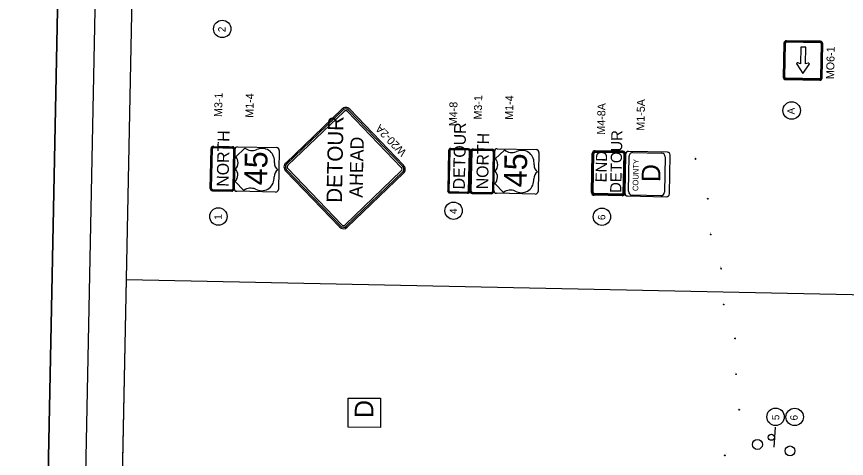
# Model space of a CAD drawing. Extents: x 327762 to 372792, y 127949 to 259367.
# Drawn here: x 344443 to 358431, y 195702 to 203152 of the extents above; entities that cross this region are included whole.
import ezdxf

# ---------------------------------------------------------------- set-up
doc = ezdxf.new("R2010")
doc.units = 0
for name, color, linetype in [('CA-TEXT', 7, 'Continuous'), ('CE-TOPO-CONC-SLAB', 7, 'Continuous'), ('E_SOIL_BORE1 [KAPUR_CADDS_LEVELS]', 7, 'Continuous'), ('E_SOIL_BORE2 [KAPUR_CADDS_LEVELS]', 7, 'Continuous'), ('P_MARK', 7, 'Continuous'), ('P_MISC_NoPlot', 7, 'Continuous'), ('P_RDWY_Text', 7, 'Continuous'), ('P_SGN_Cell', 7, 'Continuous'), ('PLT_Sheet_Border', 7, 'Continuous'), ('PLT_Sheet_Info', 7, 'Continuous'), ('SIGNS-POLES', 7, 'Continuous')]:
    doc.layers.add(name, color=color, linetype=linetype)

msp = doc.modelspace()

# ---------------------------------------------------------------- linework, layer by layer
at = {"layer": 'CA-TEXT'}
msp.add_line((350299, 196481), (350299, 196481), dxfattribs=at)
msp.add_lwpolyline([(350578, 196224), (350031, 196226), (350033, 196717), (350580, 196715)], close=True, dxfattribs=at)
for centre in [(347909, 202944), (357509, 201568), (347845, 199781), (351809, 199878), (354310, 199777), (357237, 196403), (357559, 196401)]:
    msp.add_circle(centre, 147, dxfattribs=at)
at = {"layer": 'CE-TOPO-CONC-SLAB'}
for centre in [(356932, 195937), (357481, 195828)]:
    msp.add_circle(centre, 83.7, dxfattribs=at)
at = {"layer": 'P_MARK'}
for p, q in [((355883, 200752), (355893, 200752)), ((355888, 200757), (355888, 200747)), ((356091, 200081), (356101, 200081)), ((356096, 200086), (356096, 200076)), ((356144, 199481), (356144, 199471)), ((356139, 199476), (356149, 199476)), ((356314, 198901), (356324, 198901)), ((356319, 198906), (356319, 198896)), ((356359, 198295), (356369, 198295)), ((356364, 198300), (356364, 198290)), ((356549, 197724), (356559, 197724)), ((356554, 197729), (356554, 197719)), ((356567, 197121), (356577, 197121)), ((356572, 197126), (356572, 197116)), ((356618, 196522), (356628, 196522)), ((356623, 196527), (356623, 196517)), ((356377, 195752), (356387, 195752)), ((356382, 195757), (356382, 195747))]:
    msp.add_line(p, q, dxfattribs=at)
for centre in [(355888, 200752), (356096, 200081), (356144, 199476), (356319, 198901), (356364, 198295), (356554, 197724), (356572, 197121), (356623, 196522), (356382, 195752)]:
    msp.add_circle(centre, 5, dxfattribs=at)
for centre, radius, start, end in [((355888, 200752), 4.5, 89.9869, 179.9869), ((355888, 200752), 4, 89.9869, 179.9869), ((355888, 200752), 3.5, 89.9869, 179.9869), ((355888, 200752), 3, 89.9869, 179.9869), ((355888, 200752), 2.5, 89.9869, 179.9869), ((355888, 200752), 2, 89.9869, 179.9869), ((355888, 200752), 1.5, 89.9869, 179.9869), ((355888, 200752), 1, 89.9869, 179.9869), ((355888, 200752), 0.5, 89.9869, 179.9869), ((355888, 200752), 4.5, 269.9869, 359.9869), ((355888, 200752), 4, 269.9869, 359.9869), ((355888, 200752), 3.5, 269.9869, 359.9869), ((355888, 200752), 3, 269.9869, 359.9869), ((355888, 200752), 2.5, 269.9869, 359.9869), ((355888, 200752), 2, 269.9869, 359.9869), ((355888, 200752), 1.5, 269.9869, 359.9869), ((355888, 200752), 1, 269.9869, 359.9869), ((355888, 200752), 0.5, 269.9869, 359.9869), ((356096, 200081), 4.5, 89.9869, 179.9869), ((356096, 200081), 4, 89.9869, 179.9869), ((356096, 200081), 3.5, 89.9869, 179.9869), ((356096, 200081), 3, 89.9869, 179.9869), ((356096, 200081), 2.5, 89.9869, 179.9869), ((356096, 200081), 2, 89.9869, 179.9869), ((356096, 200081), 1.5, 89.9869, 179.9869), ((356096, 200081), 1, 89.9869, 179.9869), ((356096, 200081), 0.5, 89.9869, 179.9869), ((356096, 200081), 4.5, 269.9869, 359.9869), ((356096, 200081), 4, 269.9869, 359.9869), ((356096, 200081), 3.5, 269.9869, 359.9869), ((356096, 200081), 3, 269.9869, 359.9869), ((356096, 200081), 2.5, 269.9869, 359.9869), ((356096, 200081), 2, 269.9869, 359.9869), ((356096, 200081), 1.5, 269.9869, 359.9869), ((356096, 200081), 1, 269.9869, 359.9869), ((356096, 200081), 0.5, 269.9869, 359.9869), ((356144, 199476), 4.5, 89.9869, 179.9869), ((356144, 199476), 4, 89.9869, 179.9869), ((356144, 199476), 3.5, 89.9869, 179.9869), ((356144, 199476), 3, 89.9869, 179.9869), ((356144, 199476), 2.5, 89.9869, 179.9869), ((356144, 199476), 2, 89.9869, 179.9869), ((356144, 199476), 1.5, 89.9869, 179.9869), ((356144, 199476), 1, 89.9869, 179.9869), ((356144, 199476), 0.5, 89.9869, 179.9869), ((356144, 199476), 4.5, 269.9869, 359.9869), ((356144, 199476), 4, 269.9869, 359.9869), ((356144, 199476), 3.5, 269.9869, 359.9869), ((356144, 199476), 3, 269.9869, 359.9869), ((356144, 199476), 2.5, 269.9869, 359.9869), ((356144, 199476), 2, 269.9869, 359.9869), ((356144, 199476), 1.5, 269.9869, 359.9869), ((356144, 199476), 1, 269.9869, 359.9869), ((356144, 199476), 0.5, 269.9869, 359.9869), ((356319, 198901), 4.5, 89.9869, 179.9869), ((356319, 198901), 4, 89.9869, 179.9869), ((356319, 198901), 3.5, 89.9869, 179.9869), ((356319, 198901), 3, 89.9869, 179.9869), ((356319, 198901), 2.5, 89.9869, 179.9869), ((356319, 198901), 2, 89.9869, 179.9869), ((356319, 198901), 1.5, 89.9869, 179.9869), ((356319, 198901), 1, 89.9869, 179.9869), ((356319, 198901), 0.5, 89.9869, 179.9869), ((356319, 198901), 4.5, 269.9869, 359.9869), ((356319, 198901), 4, 269.9869, 359.9869), ((356319, 198901), 3.5, 269.9869, 359.9869), ((356319, 198901), 3, 269.9869, 359.9869), ((356319, 198901), 2.5, 269.9869, 359.9869), ((356319, 198901), 2, 269.9869, 359.9869), ((356319, 198901), 1.5, 269.9869, 359.9869), ((356319, 198901), 1, 269.9869, 359.9869), ((356319, 198901), 0.5, 269.9869, 359.9869), ((356364, 198295), 4.5, 89.9869, 179.9869), ((356364, 198295), 4, 89.9869, 179.9869), ((356364, 198295), 3.5, 89.9869, 179.9869), ((356364, 198295), 3, 89.9869, 179.9869), ((356364, 198295), 2.5, 89.9869, 179.9869), ((356364, 198295), 2, 89.9869, 179.9869), ((356364, 198295), 1.5, 89.9869, 179.9869), ((356364, 198295), 1, 89.9869, 179.9869), ((356364, 198295), 0.5, 89.9869, 179.9869), ((356364, 198295), 4.5, 269.9869, 359.9869), ((356364, 198295), 4, 269.9869, 359.9869), ((356364, 198295), 3.5, 269.9869, 359.9869), ((356364, 198295), 3, 269.9869, 359.9869), ((356364, 198295), 2.5, 269.9869, 359.9869), ((356364, 198295), 2, 269.9869, 359.9869), ((356364, 198295), 1.5, 269.9869, 359.9869), ((356364, 198295), 1, 269.9869, 359.9869), ((356364, 198295), 0.5, 269.9869, 359.9869), ((356554, 197724), 4.5, 89.9869, 179.9869), ((356554, 197724), 4, 89.9869, 179.9869), ((356554, 197724), 3.5, 89.9869, 179.9869), ((356554, 197724), 3, 89.9869, 179.9869), ((356554, 197724), 2.5, 89.9869, 179.9869), ((356554, 197724), 2, 89.9869, 179.9869), ((356554, 197724), 1.5, 89.9869, 179.9869), ((356554, 197724), 1, 89.9869, 179.9869), ((356554, 197724), 0.5, 89.9869, 179.9869), ((356554, 197724), 4.5, 269.9869, 359.9869), ((356554, 197724), 4, 269.9869, 359.9869), ((356554, 197724), 3.5, 269.9869, 359.9869), ((356554, 197724), 3, 269.9869, 359.9869), ((356554, 197724), 2.5, 269.9869, 359.9869), ((356554, 197724), 2, 269.9869, 359.9869), ((356554, 197724), 1.5, 269.9869, 359.9869), ((356554, 197724), 1, 269.9869, 359.9869), ((356554, 197724), 0.5, 269.9869, 359.9869), ((356572, 197121), 4.5, 89.9869, 179.9869), ((356572, 197121), 4, 89.9869, 179.9869), ((356572, 197121), 3.5, 89.9869, 179.9869), ((356572, 197121), 3, 89.9869, 179.9869), ((356572, 197121), 2.5, 89.9869, 179.9869), ((356572, 197121), 2, 89.9869, 179.9869), ((356572, 197121), 1.5, 89.9869, 179.9869), ((356572, 197121), 1, 89.9869, 179.9869), ((356572, 197121), 4.5, 269.9869, 359.9869), ((356572, 197121), 4, 269.9869, 359.9869), ((356572, 197121), 3.5, 269.9869, 359.9869), ((356572, 197121), 3, 269.9869, 359.9869), ((356572, 197121), 2.5, 269.9869, 359.9869), ((356572, 197121), 2, 269.9869, 359.9869), ((356572, 197121), 1.5, 269.9869, 359.9869), ((356572, 197121), 1, 269.9869, 359.9869), ((356572, 197121), 0.5, 269.9869, 359.9869), ((356572, 197121), 0.5, 89.9869, 179.9869), ((356623, 196522), 4.5, 89.9869, 179.9869), ((356623, 196522), 4, 89.9869, 179.9869), ((356623, 196522), 3.5, 89.9869, 179.9869), ((356623, 196522), 3, 89.9869, 179.9869), ((356623, 196522), 2.5, 89.9869, 179.9869), ((356623, 196522), 2, 89.9869, 179.9869), ((356623, 196522), 1.5, 89.9869, 179.9869), ((356623, 196522), 1, 89.9869, 179.9869), ((356623, 196522), 0.5, 89.9869, 179.9869), ((356623, 196522), 4.5, 269.9869, 359.9869), ((356623, 196522), 4, 269.9869, 359.9869), ((356623, 196522), 3.5, 269.9869, 359.9869), ((356623, 196522), 3, 269.9869, 359.9869), ((356623, 196522), 2.5, 269.9869, 359.9869), ((356623, 196522), 2, 269.9869, 359.9869), ((356623, 196522), 1.5, 269.9869, 359.9869), ((356623, 196522), 1, 269.9869, 359.9869), ((356623, 196522), 0.5, 269.9869, 359.9869), ((356382, 195752), 4.5, 89.9869, 179.9869), ((356382, 195752), 4, 89.9869, 179.9869), ((356382, 195752), 3.5, 89.9869, 179.9869), ((356382, 195752), 3, 89.9869, 179.9869), ((356382, 195752), 2.5, 89.9869, 179.9869), ((356382, 195752), 2, 89.9869, 179.9869), ((356382, 195752), 1.5, 89.9869, 179.9869), ((356382, 195752), 1, 89.9869, 179.9869), ((356382, 195752), 0.5, 89.9869, 179.9869), ((356382, 195752), 4.5, 269.9869, 359.9869), ((356382, 195752), 4, 269.9869, 359.9869), ((356382, 195752), 3.5, 269.9869, 359.9869), ((356382, 195752), 3, 269.9869, 359.9869), ((356382, 195752), 2.5, 269.9869, 359.9869), ((356382, 195752), 2, 269.9869, 359.9869), ((356382, 195752), 1.5, 269.9869, 359.9869), ((356382, 195752), 1, 269.9869, 359.9869), ((356382, 195752), 0.5, 269.9869, 359.9869)]:
    msp.add_arc(centre, radius, start, end, dxfattribs=at)
at = {"layer": 'P_MISC_NoPlot'}
msp.add_lwpolyline([(345724, 170440), (346294, 198721), (365051, 198328), (365036, 197298), (370642, 197202), (370093, 169949)], close=True, dxfattribs=at)
at = {"layer": 'P_RDWY_Text'}
msp.add_lwpolyline([(344443, 168885), (345298, 211374), (372792, 210820), (371936, 168331)], close=True, dxfattribs=at)
at = {"layer": 'P_SGN_Cell'}
for p, q in [((357378, 202706), (357366, 202132)), ((357377, 202132), (357389, 202706)), ((357391, 202132), (357403, 202706)), ((357993, 202710), (357419, 202722)), ((357994, 202735), (357420, 202746)), ((357994, 202724), (357420, 202735)), ((357664, 202637), (357658, 202357)), ((357746, 202636), (357664, 202637)), ((357740, 202356), (357746, 202636)), ((357998, 202119), (358010, 202693)), ((358012, 202119), (358023, 202693)), ((358023, 202119), (358034, 202693)), ((357593, 202348), (357696, 202191)), ((357658, 202357), (357611, 202373)), ((357696, 202191), (357805, 202344)), ((357788, 202369), (357740, 202356)), ((357981, 202103), (357407, 202115)), ((357981, 202090), (357407, 202101)), ((357407, 202090), (357981, 202079)), ((347708, 200252), (347721, 200928)), ((347717, 200252), (347731, 200927)), ((347730, 200252), (347743, 200927)), ((347759, 200955), (348084, 200948)), ((347759, 200942), (348084, 200936)), ((347760, 200964), (348084, 200958)), ((348099, 200920), (348086, 200245)), ((348112, 200920), (348098, 200245)), ((348121, 200919), (348108, 200245)), ((348108, 200254), (348121, 200910)), ((348288, 200936), (348136, 200790)), ((348169, 200956), (348825, 200943)), ((348871, 200895), (348864, 200567)), ((348871, 200895), (348871, 200895)), ((352085, 200209), (352098, 200884)), ((352094, 200209), (352107, 200884)), ((352106, 200209), (352120, 200884)), ((352136, 200921), (352461, 200915)), ((352136, 200912), (352461, 200905)), ((352136, 200899), (352461, 200893)), ((352476, 200877), (352463, 200202)), ((352489, 200876), (352475, 200202)), ((352498, 200876), (352484, 200201)), ((352485, 200220), (352498, 200877)), ((352665, 200902), (352513, 200756)), ((352546, 200922), (353202, 200909)), ((354664, 200880), (354196, 200889)), ((354664, 200868), (354196, 200878)), ((355414, 200865), (354758, 200878)), ((353248, 200861), (353241, 200533)), ((353248, 200861), (353248, 200861)), ((354135, 200187), (354148, 200843)), ((354147, 200187), (354160, 200843)), ((354162, 200187), (354175, 200843)), ((354664, 200852), (354195, 200862)), ((354670, 200176), (354683, 200833)), ((354685, 200176), (354699, 200832)), ((354697, 200176), (354710, 200832)), ((354710, 200832), (354697, 200176)), ((354756, 200206), (354768, 200800)), ((354832, 200861), (355316, 200851)), ((355378, 200787), (355366, 200194)), ((355447, 200161), (355460, 200817)), ((348789, 200688), (348790, 200717)), ((353166, 200654), (353167, 200684)), ((348864, 200567), (348858, 200239)), ((353241, 200533), (353235, 200205)), ((348128, 200373), (348273, 200222)), ((348784, 200420), (348784, 200449)), ((352505, 200340), (352650, 200188)), ((353161, 200386), (353161, 200416)), ((347744, 200214), (348069, 200208)), ((347745, 200236), (348070, 200230)), ((347745, 200224), (348070, 200217)), ((348810, 200193), (348154, 200206)), ((352121, 200181), (352446, 200174)), ((352122, 200193), (352447, 200187)), ((352121, 200171), (352446, 200165)), ((353187, 200159), (352531, 200173)), ((354650, 200157), (354181, 200167)), ((354650, 200142), (354181, 200151)), ((354649, 200130), (354181, 200139)), ((354743, 200128), (355399, 200115)), ((355302, 200132), (354818, 200142)), ((355302, 200132), (355302, 200132))]:
    msp.add_line(p, q, dxfattribs=at)
for points in [[(349925, 201592), (348979, 200683)], [(349942, 201575), (348995, 200666)], [(350966, 200644), (350058, 201590)], [(349963, 201554), (349016, 200645)], [(350928, 200607), (350019, 201553)], [(350949, 200628), (350040, 201574)], [(351723, 200892), (351710, 200217)], [(351733, 200891), (351719, 200217)], [(351745, 200891), (351731, 200216)], [(352061, 200922), (351761, 200928)], [(352061, 200913), (351761, 200919)], [(352061, 200900), (351761, 200907)], [(352063, 200210), (352076, 200885)], [(352075, 200209), (352089, 200884)], [(352085, 200209), (352098, 200884)], [(348976, 200551), (349885, 199604)], [(348993, 200567), (349903, 199621)], [(349015, 200588), (349924, 199641)], [(349981, 199640), (350927, 200549)], [(350001, 199619), (350948, 200528)], [(350018, 199602), (350964, 200511)], [(351746, 200179), (352046, 200173)], [(351747, 200200), (352047, 200194)], [(351747, 200188), (352046, 200182)]]:
    msp.add_lwpolyline(points, dxfattribs=at)
for centre, radius, start, end in [((357419, 202705), 41, 88.8462, 178.8462), ((357419, 202705), 30.1, 88.8462, 178.8462), ((357419, 202705), 16.4, 88.8462, 178.8462), ((357993, 202694), 16.4, 358.8462, 88.8462), ((357993, 202694), 41, 358.8462, 88.8462), ((357993, 202694), 30.1, 358.8462, 88.8462), ((357606, 202357), 16.4, 72.0436, 213.3759), ((357792, 202353), 16.4, 324.3166, 105.6488), ((357408, 202131), 41, 178.8462, 268.8462), ((357408, 202131), 30.1, 178.8462, 268.8462), ((357408, 202131), 41, 239.4497, 268.8462), ((357408, 202131), 16.4, 178.8462, 268.8462), ((357982, 202120), 30.1, 268.8462, 358.8462), ((357982, 202120), 41, 268.8462, 358.8462), ((357982, 202120), 16.4, 268.8462, 358.8462), ((349990, 201525), 93.7, 43.8468, 133.8468), ((349990, 201525), 69.9, 43.8468, 133.8468), ((349990, 201525), 40.2, 43.8468, 133.8468), ((347759, 200927), 37.5, 88.8462, 178.8462), ((347759, 200927), 28.1, 88.8462, 178.8462), ((347759, 200927), 15.6, 88.8462, 178.8462), ((348084, 200920), 37.5, 358.8462, 88.8462), ((348084, 200920), 28.1, 358.8462, 88.8462), ((348084, 200920), 15.6, 358.8462, 88.8462), ((348168, 200909), 46.9, 88.8462, 178.8462), ((348413, 201102), 208, 233.1143, 291.9873), ((348581, 200721), 208, 358.8462, 115.6928), ((348824, 200896), 46.9, 358.8462, 88.8462), ((351761, 200891), 37.5, 88.8468, 178.8468), ((351761, 200891), 28.1, 88.8468, 178.8468), ((351761, 200891), 15.6, 88.8468, 178.8468), ((352061, 200885), 37.5, 358.8468, 88.8468), ((352061, 200885), 28.1, 358.8468, 88.8468), ((352061, 200885), 15.6, 358.8468, 88.8468), ((352136, 200884), 37.5, 88.8462, 178.8462), ((352136, 200884), 28.1, 88.8462, 178.8462), ((352136, 200884), 15.6, 88.8462, 178.8462), ((352461, 200877), 37.5, 358.8462, 88.8462), ((352461, 200877), 28.1, 358.8462, 88.8462), ((352461, 200877), 15.6, 358.8462, 88.8462), ((352545, 200876), 46.9, 88.8462, 178.8462), ((352790, 201069), 208, 233.1143, 291.9873), ((352958, 200688), 208, 358.8462, 115.6928), ((353201, 200862), 46.9, 358.8462, 88.8462), ((354195, 200842), 46.9, 88.8468, 178.8468), ((354195, 200842), 35.2, 88.8468, 178.8468), ((354664, 200833), 46.9, 358.8468, 88.8468), ((354757, 200831), 46.9, 88.8462, 178.8462), ((348028, 200688), 149, 314.4191, 43.2734), ((352405, 200654), 149, 314.4191, 43.2734), ((354195, 200842), 19.5, 88.8468, 178.8468), ((354664, 200833), 35.2, 358.8468, 88.8468), ((354664, 200833), 19.5, 358.8468, 88.8468), ((354831, 200798), 62.5, 88.8462, 178.8462), ((355315, 200789), 62.5, 358.8462, 88.8462), ((355413, 200818), 46.9, 358.8462, 88.8462), ((348940, 200685), 151, 179.1885, 231.634), ((349044, 200616), 93.7, 133.8449, 223.8468), ((349044, 200616), 69.9, 133.8449, 223.8468), ((349044, 200616), 40.2, 133.8449, 223.8468), ((350900, 200578), 40.2, 313.854, 44.4977), ((350900, 200578), 69.9, 313.854, 44.4977), ((350900, 200578), 93.7, 313.854, 44.4977), ((353317, 200652), 151, 179.1885, 231.634), ((348023, 200480), 149, 314.4191, 43.2734), ((348935, 200446), 151, 126.0584, 178.5039), ((352401, 200446), 149, 314.4191, 43.2734), ((353312, 200412), 151, 126.0584, 178.5039), ((348575, 200424), 208, 240.0981, 358.8463), ((352952, 200390), 208, 240.0981, 358.8463), ((347745, 200252), 37.5, 179.6119, 268.8462), ((347745, 200252), 28.1, 178.8462, 268.8462), ((347745, 200252), 15.6, 178.8462, 268.8462), ((348070, 200245), 37.5, 268.8462, 358.8462), ((348070, 200245), 28.1, 268.8462, 358.8462), ((348070, 200245), 15.6, 268.8462, 358.8462), ((348155, 200253), 46.9, 178.8462, 268.8462), ((348392, 200050), 208, 67.7159, 124.7982), ((348811, 200240), 46.9, 268.8462, 358.8462), ((351747, 200216), 37.5, 178.8468, 268.8468), ((351747, 200216), 28.1, 178.8468, 268.8468), ((351747, 200216), 15.6, 178.8468, 268.8468), ((351747, 200216), 15.6, 178.8468, 186.1883), ((352047, 200210), 37.5, 268.8468, 358.8468), ((352047, 200210), 28.1, 268.8468, 358.8468), ((352047, 200210), 15.6, 268.8468, 358.8468), ((352122, 200209), 37.5, 179.6119, 268.8462), ((352122, 200209), 28.1, 178.8462, 268.8462), ((352122, 200209), 15.6, 178.8462, 268.8462), ((352447, 200202), 28.1, 268.8462, 358.8462), ((352447, 200202), 37.5, 268.8462, 358.8462), ((352447, 200202), 15.6, 268.8462, 358.8462), ((352532, 200220), 46.9, 178.8462, 268.8462), ((352769, 200017), 208, 67.7159, 124.7982), ((353188, 200206), 46.9, 268.8462, 358.8462), ((354182, 200186), 46.9, 178.8468, 268.8468), ((354182, 200186), 35.2, 178.8468, 268.8468), ((354182, 200186), 19.5, 178.8468, 268.8468), ((354182, 200186), 19.5, 178.8468, 187.6911), ((354650, 200177), 35.2, 268.8468, 358.8468), ((354650, 200177), 19.5, 268.8468, 358.8468), ((354819, 200205), 62.5, 178.8462, 268.8462), ((355303, 200195), 62.5, 268.8462, 358.8462), ((354650, 200177), 46.9, 268.8468, 358.8468), ((354744, 200175), 46.9, 178.8462, 268.8462), ((355400, 200162), 46.9, 268.8462, 358.8462), ((349953, 199669), 69.9, 223.8468, 313.8468), ((349953, 199669), 40.2, 223.8468, 313.8468), ((349953, 199669), 93.7, 223.8468, 313.8468)]:
    msp.add_arc(centre, radius, start, end, dxfattribs=at)
at = {"layer": 'PLT_Sheet_Border'}
for points in [[(371936, 168331), (372792, 210820), (345298, 211374), (344443, 168885)], [(371317, 168643), (372150, 210008), (345907, 210537), (345074, 169172)]]:
    msp.add_lwpolyline(points, close=True, dxfattribs=at)
at = {"layer": 'PLT_Sheet_Info'}
msp.add_line((345724, 170440), (346517, 209806), dxfattribs=at)
at = {"layer": 'SIGNS-POLES'}
for p, q in [((357230, 196227), (357220, 196059)), ((357219, 196057), (357208, 195889))]:
    msp.add_line(p, q, dxfattribs=at)
msp.add_circle((357167, 196059), 52.2, dxfattribs=at)

# ---------------------------------------------------------------- texts
at = {"layer": 'CA-TEXT'}
for s, height, rotation, p in [('2', 125, 88.8468, (347965, 202888)), ('A', 125, 88.8468, (357557, 201502)), ('4', 125, 88.8468, (351865, 199822)), ('1', 125, 88.8468, (347901, 199725)), ('6', 125, 88.8468, (354366, 199720)), ('D', 312, 89.767, (350455, 196384)), ('5', 125, 88.8468, (357299, 196345)), ('6', 125, 88.8468, (357608, 196341))]:
    msp.add_text(s, height=height, rotation=rotation, dxfattribs=at).set_placement(p)
at = {"layer": 'E_SOIL_BORE1 [KAPUR_CADDS_LEVELS]'}
for s, rotation, p in [('B127', 102.6348, (356146, 199484)), ('B128', 102.6348, (356323, 198909)), ('B125', 102.6348, (356367, 198303)), ('B124', 89.9869, (356628, 196529)), ('B121', 61.5935, (356391, 195758))]:
    msp.add_text(s, height=10, rotation=rotation, dxfattribs=at).set_placement(p)
at = {"layer": 'E_SOIL_BORE2 [KAPUR_CADDS_LEVELS]'}
for s, rotation, p in [('B129', 102.6348, (355891, 200759)), ('B130', 102.6348, (356106, 200090)), ('B126', 102.6348, (356557, 197732)), ('B123', 89.9869, (356576, 197129))]:
    msp.add_text(s, height=10, rotation=rotation, dxfattribs=at).set_placement(p)
at = {"layer": 'P_SGN_Cell'}
for s, height, rotation, p in [('MO6-1', 135, 88.8462, (358224, 202096)), ('M3-1', 135, 88.8462, (347907, 201458)), ('M1-4', 135, 88.8462, (348434, 201445)), ('M3-1', 135, 88.8462, (352284, 201415)), ('M1-4', 135, 88.8462, (352811, 201411)), ('M1-5A', 135, 88.8462, (355026, 201228)), ('M4-8', 135, 88.8468, (351867, 201303)), ('M4-8A', 135, 88.8468, (354361, 201160)), ('DETOUR', 258.9, 88.8468, (349925, 200011)), ('W20-2A', 135, 133.8468, (351026, 200874)), ('DETOUR', 200, 88.8468, (351998, 200236)), ('NORTH', 200, 88.8462, (348015, 200281)), ('NORTH', 200, 88.8462, (352391, 200238)), ('DETOUR', 187.5, 88.8468, (354635, 200177)), ('AHEAD', 223.2, 88.8468, (350275, 200096)), ('45', 383.3, 88.8462, (348663, 200306)), ('45', 383.3, 88.8462, (353040, 200272)), ('END', 187.5, 88.8468, (354388, 200355)), ('COUNTY', 95.8, 88.8462, (354922, 200209)), ('D', 313, 88.8462, (355291, 200359))]:
    msp.add_text(s, height=height, rotation=rotation, dxfattribs=at).set_placement(p)

doc.saveas('drawing.dxf')
